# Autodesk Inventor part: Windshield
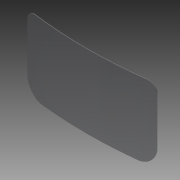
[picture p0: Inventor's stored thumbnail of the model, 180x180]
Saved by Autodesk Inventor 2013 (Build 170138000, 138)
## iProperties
Created: 2006-03
Part Number: Windshield
Document SubType Name: Modeling
Designer: Autodesk, Inc.
Mass: 21946 g
Surface Area: 25523.6 cm^2
Volume: 10067 cm^3
Density: 2.18 g/cm^3
Material: Glass
Author: Autodesk, Inc.
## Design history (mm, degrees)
sketch "Sketch1"
  geometry: L1 (0, 5943.43)-(0, -1056.57) reference; L2 (-1050, 0)-(1050, 0) reference; A1 r 5000 centre (0, 4943.43) between (-750, 0) and (750, 0); 1 further point
  constraints: 3 point on line, 2 point on circle, 1 centre point
  dimensions: "d0" = 1500 distance of A1.end A1.start; "d2" = 5000 radius of A1
workplane "Work Plane1"
sketch "Sketch2"
  geometry: L1 (-4, 425)-(4, 425); L2 (4, 425)-(4, -425); L3 (4, -425)-(-4, -425); L4 (-4, -425)-(-4, 425); L5 (-4, 425)-(4, -425); 3 further points
  constraints: 10 end point, 2 parallel, 1 coincident, 1 horizontal, 1 midpoint, 1 perpendicular
  dimensions: "d3" = 8 distance of L1.start L1.end; "d4" = 850 distance of L1.end L2.end
sweep "Sweep1" sketch "Sketch2" dims "d5" = 0
fillet "Fillet1" dims "d6" = 100
fillet "Fillet2" dims "d7" = 200
body "Solid1"
